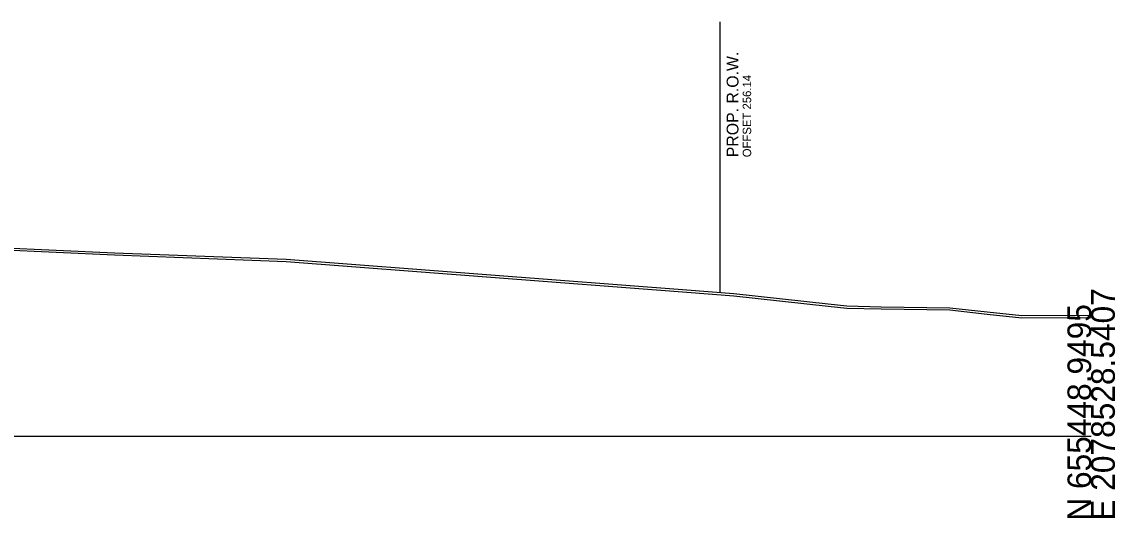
# Model space of a CAD drawing. Extents: x 1131015 to 1136271, y 133453 to 174329.
# Drawn here: x 1131514 to 1131643.3, y 154658 to 154716.6 of the extents above; entities that cross this region are included whole.
import ezdxf

# ---------------------------------------------------------------- set-up
doc = ezdxf.new("R2010")
doc.units = 0
for name, color, linetype in [('DESIGN - ROW - Right-of-Way and Easement Labels', 7, 'Continuous'), ('DESIGN - ROW - Right-of-Way Linework', 7, 'Continuous'), ('DESIGN - SHEET - Light Grid', 7, 'Continuous'), ('SURVEY - GROUND - Bottom of Topsoil Layer', 7, 'Continuous'), ('SURVEY - GROUND - Top of Ground', 7, 'Continuous')]:
    doc.layers.add(name, color=color, linetype=linetype)

msp = doc.modelspace()

# ---------------------------------------------------------------- linework, layer by layer
at = {"layer": 'DESIGN - ROW - Right-of-Way Linework'}
msp.add_line((1131596.6, 154684.63), (1131596.6, 154716.63), dxfattribs=at)
at = {"layer": 'DESIGN - SHEET - Light Grid'}
msp.add_line((1131340.46, 154667.66), (1131640.46, 154667.66), dxfattribs=at)
at = {"layer": 'SURVEY - GROUND - Bottom of Topsoil Layer'}
for p, q in [((1131496.65, 154690.36), (1131524.97, 154689.08)), ((1131524.97, 154689.08), (1131545.24, 154688.31)), ((1131545.24, 154688.31), (1131592.64, 154684.69)), ((1131592.64, 154684.69), (1131598.21, 154684.26)), ((1131598.21, 154684.26), (1131609.37, 154683.03)), ((1131609.37, 154683.03), (1131611.56, 154682.8)), ((1131611.56, 154682.8), (1131615.63, 154682.71)), ((1131615.63, 154682.71), (1131623.76, 154682.58)), ((1131623.76, 154682.58), (1131628.16, 154682.09)), ((1131628.16, 154682.09), (1131632.27, 154681.65)), ((1131632.27, 154681.65), (1131640.46, 154681.7))]:
    msp.add_line(p, q, dxfattribs=at)
at = {"layer": 'SURVEY - GROUND - Top of Ground'}
for p, q in [((1131496.65, 154690.61), (1131524.97, 154689.33)), ((1131524.97, 154689.33), (1131545.24, 154688.56)), ((1131545.24, 154688.56), (1131592.64, 154684.94)), ((1131592.64, 154684.94), (1131598.21, 154684.51)), ((1131598.21, 154684.51), (1131609.37, 154683.28)), ((1131609.37, 154683.28), (1131611.56, 154683.05)), ((1131611.56, 154683.05), (1131615.63, 154682.96)), ((1131615.63, 154682.96), (1131623.76, 154682.83)), ((1131623.76, 154682.83), (1131628.16, 154682.34)), ((1131628.16, 154682.34), (1131632.27, 154681.9)), ((1131632.27, 154681.9), (1131640.46, 154681.95))]:
    msp.add_line(p, q, dxfattribs=at)

# ---------------------------------------------------------------- texts
at = {"layer": 'DESIGN - ROW - Right-of-Way and Easement Labels'}
for s, height, p in [('PROP. R.O.W.', 1.4, (1131598.75, 154700.63)), ('OFFSET 256.14', 1, (1131600.25, 154700.63))]:
    msp.add_text(s, height=height, rotation=90, dxfattribs=at).set_placement(p)
at = {"layer": 'DESIGN - SHEET - Light Grid'}
for s, p in [('E 2078528.5407', (1131643.26, 154657.66)), ('N 655448.9495', (1131640.46, 154657.66))]:
    msp.add_text(s, height=2.8, rotation=90, dxfattribs=at).set_placement(p)

doc.saveas('drawing.dxf')
